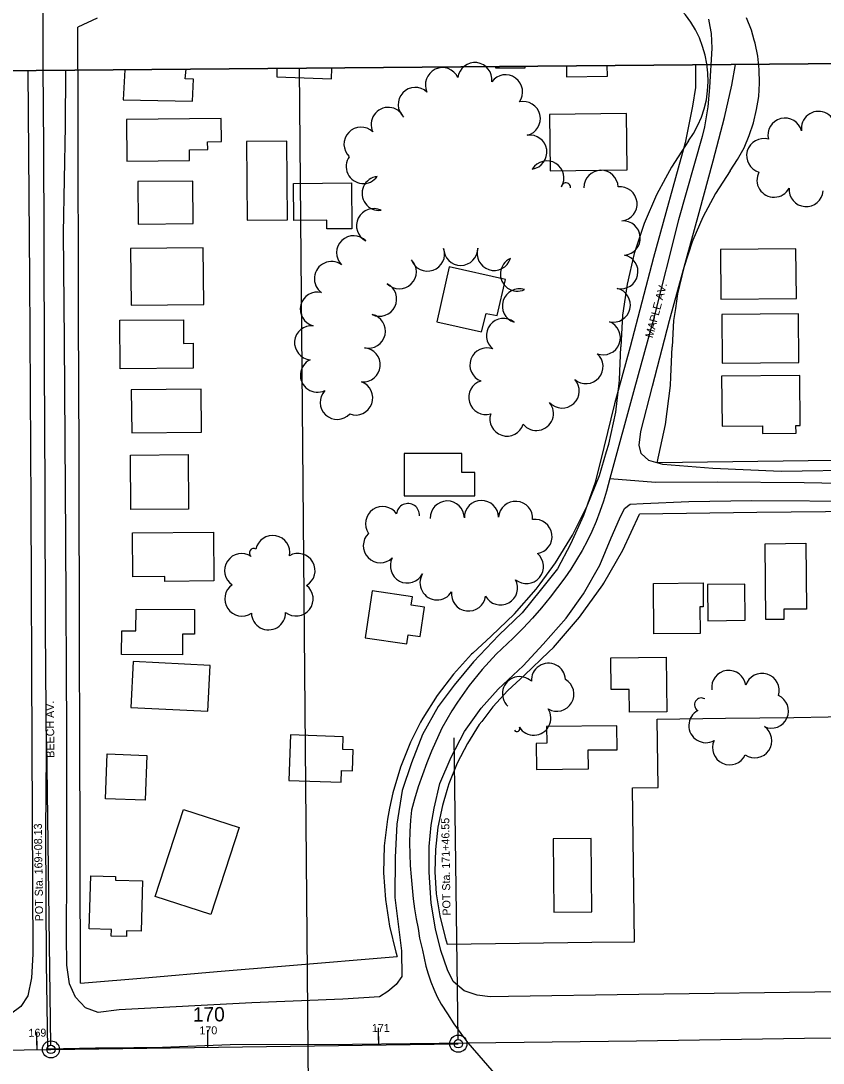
# Model space of a CAD drawing. Extents: x -2233 to 187241, y 4582 to 150524.
# Drawn here: x 116828 to 117297, y 59523 to 60132 of the extents above; entities that cross this region are included whole.
import ezdxf

# ---------------------------------------------------------------- set-up
doc = ezdxf.new("R2010")
doc.units = 0
for name, color, linetype in [('60', 7, 'Continuous'), ('BLDG', 7, 'Continuous'), ('GE_X_CL_100', 7, 'Continuous'), ('GE_X_CL_20', 7, 'Continuous'), ('GE_X_CL_2000', 7, 'Continuous'), ('GE_X_CL_50', 7, 'Continuous'), ('GRID', 7, 'Continuous'), ('ROAD', 7, 'Continuous'), ('ROAD-NAME', 7, 'Continuous'), ('RW_X_Fee_RW', 7, 'Continuous'), ('TREES', 7, 'Continuous')]:
    doc.layers.add(name, color=color, linetype=linetype)

msp = doc.modelspace()

# ---------------------------------------------------------------- linework, layer by layer
at = {"layer": '60'}
msp.add_line((114990.89, 60087.23), (119990.7, 60130.86), dxfattribs=at)
at = {"layer": 'BLDG'}
for points in [[(117105.7, 60105.68), (117105.73, 60105.01), (117122.97, 60104.93), (117123, 60105.83)], [(117147.16, 60106.04), (117147.27, 60099.76), (117171.27, 60100.08), (117171.06, 60106.25)], [(116888.84, 60103.79), (116887.88, 60086.19), (116928.33, 60085.4), (116928.99, 60098.28), (116924.17, 60098.45), (116924.61, 60104.1)], [(116977.78, 60104.57), (116977.8, 60099.72), (117009.7, 60098.52), (117009.87, 60104.85)]]:
    msp.add_lwpolyline(points, dxfattribs=at)
for points in [[(116889.9, 60050.42), (116926.65, 60050.74), (116926.6, 60057.08), (116937.26, 60057.17), (116937.22, 60061.72), (116945.35, 60061.79), (116945.23, 60075.25), (116889.68, 60074.77)], [(117137.78, 60044.74), (117182.74, 60045.29), (117182.34, 60078.21), (117137.37, 60077.65)], [(116983.93, 60016.1), (116983.53, 60062.14), (116960.06, 60061.93), (116960.46, 60015.89)], [(116896.63, 60013.54), (116928.79, 60013.83), (116928.57, 60038.77), (116896.41, 60038.49)], [(117021.39, 60037.61), (117021.63, 60010.89), (117007.04, 60010.76), (117006.99, 60015.84), (116987.67, 60015.67), (116987.48, 60037.32)], [(116892.45, 59966.12), (116935, 59966.49), (116934.71, 59999.65), (116892.16, 59999.28)], [(117237.64, 59969.63), (117281.76, 59970.01), (117281.51, 59999.18), (117237.39, 59998.8)], [(117071.34, 59956.47), (117097.57, 59950.55), (117100.19, 59961.34), (117106.69, 59960.09), (117111.46, 59981.19), (117078.59, 59988.6)], [(117238.4, 59932.21), (117283.31, 59932.61), (117283.06, 59961.14), (117238.15, 59960.74)], [(116885.86, 59957.3), (116923.08, 59957.62), (116923.2, 59943.81), (116928.68, 59943.86), (116928.8, 59929.31), (116886.11, 59928.94)], [(117238.27, 59895.41), (117261.88, 59895.62), (117261.92, 59891.07), (117281.57, 59891.24), (117281.53, 59895.74), (117284.08, 59895.76), (117283.83, 59924.97), (117238.02, 59924.57)], [(116892.79, 59891.55), (116933.63, 59891.9), (116933.41, 59916.97), (116892.57, 59916.62)], [(117052.32, 59854.61), (117093.61, 59854.61), (117093.61, 59868.35), (117086.08, 59868.35), (117086.08, 59879.46), (117052.32, 59879.46)], [(116925.78, 59878.71), (116926.05, 59846.84), (116892.3, 59846.54), (116892.02, 59878.42)], [(116940.88, 59804.84), (116912.2, 59804.59), (116912.18, 59807.34), (116893.5, 59807.18), (116893.27, 59833.04), (116940.63, 59833.45)], [(117287.34, 59826.84), (117287.68, 59788.38), (117274.41, 59788.26), (117274.46, 59782.3), (117263.97, 59782.21), (117263.58, 59826.63)], [(117227.14, 59803.64), (117227.26, 59789.68), (117225.36, 59789.67), (117225.5, 59774.14), (117198.36, 59773.9), (117198.1, 59803.39)], [(117251.79, 59781.79), (117251.61, 59802.86), (117229.75, 59802.67), (117229.94, 59781.59)], [(117053.85, 59768.03), (117054.62, 59773.37), (117061.68, 59772.36), (117064.16, 59789.57), (117056.43, 59790.68), (117057.13, 59795.57), (117033.44, 59798.99), (117029.48, 59771.55)], [(116887.01, 59775.7), (116895.24, 59775.64), (116895.33, 59788.4), (116929.59, 59788.15), (116929.48, 59773.74), (116922.51, 59773.79), (116922.43, 59761.59), (116886.91, 59761.84)], [(116892.35, 59730.85), (116937.35, 59728.6), (116938.68, 59755.4), (116893.68, 59757.65)], [(117205.91, 59728.17), (117184.08, 59727.98), (117183.96, 59741.38), (117173.31, 59741.29), (117173.15, 59759.93), (117205.63, 59760.21)], [(116984.74, 59688.11), (117015.31, 59687.04), (117015.56, 59694), (117022.02, 59693.77), (117022.46, 59706.08), (117016.29, 59706.3), (117016.56, 59713.66), (116985.68, 59714.74)], [(117135.65, 59709.86), (117129.5, 59709.81), (117129.63, 59694.6), (117160.11, 59694.86), (117160.01, 59705.98), (117176.86, 59706.13), (117176.74, 59720.13), (117135.56, 59719.77)], [(116901.67, 59702.72), (116900.64, 59676.55), (116877.47, 59677.45), (116878.5, 59703.62)], [(116923.12, 59671.12), (116955.62, 59660.55), (116939.06, 59609.67), (116906.56, 59620.25)], [(117162.03, 59611.31), (117161.65, 59654.23), (117139.41, 59654.04), (117139.79, 59611.11)], [(116883.3, 59631.99), (116883.24, 59629.73), (116899.18, 59629.32), (116898.43, 59599.97), (116889.77, 59600.19), (116889.68, 59596.8), (116880.78, 59597.02), (116880.88, 59601.02), (116867.98, 59601.35), (116868.78, 59632.37)]]:
    msp.add_lwpolyline(points, close=True, dxfattribs=at)
at = {"layer": 'GE_X_CL_100'}
for p, q in [((116837.41, 59530.7), (116837.27, 59540.7)), ((116937.4, 59532.09), (116937.26, 59542.09)), ((117037.39, 59533.48), (117037.25, 59543.48))]:
    msp.add_line(p, q, dxfattribs=at)
for centre in [(117083.94, 59534.13), (116845.54, 59530.81)]:
    msp.add_circle(centre, 5, dxfattribs=at)
at = {"layer": 'GE_X_CL_20'}
for p, q in [((116845.54, 59530.81), (117083.94, 59534.13)), ((116459.67, 59525.44), (116845.54, 59530.81))]:
    msp.add_line(p, q, dxfattribs=at)
at = {"layer": 'GE_X_CL_2000'}
for p, q in [((116845.54, 59530.81), (117083.94, 59534.13)), ((116459.67, 59525.44), (116845.54, 59530.81))]:
    msp.add_line(p, q, dxfattribs=at)
for points in [[(116840.71, 60140.35), (116840.76, 60105.37), (116841.17, 60058.86), (116841.41, 60004.82), (116841.52, 59931.57), (116841.96, 59857.96), (116842.08, 59777.38), (116842.69, 59704.76), (116842.25, 59657.72), (116842.7, 59581.45), (116843.55, 59531.09)], [(117230.29, 60133.4), (117231.19, 60129.25), (117231.83, 60125.06), (117232.2, 60120.83), (117232.31, 60116.48), (117230.87, 60093.51), (117229.88, 60082.08), (117229.07, 60076.27), (117228.02, 60070.49), (117226.73, 60064.77), (117212.74, 60016.05), (117198.17, 59957.94), (117186.98, 59917.69), (117172.68, 59864.81)], [(117172.68, 59864.81), (117199.4, 59862.58), (117235.41, 59862.88), (117286.3, 59862.44), (117327.41, 59861.65), (117378.43, 59862.74), (117412.31, 59864.32), (117453.32, 59865.4), (117500.32, 59866.16), (117563.97, 59866.92), (117594.05, 59867.09)], [(117172.68, 59864.81), (117170.68, 59857.42), (117168.87, 59851.44), (117166.82, 59845.47), (117164.53, 59839.59), (117162.02, 59833.81), (117159.28, 59828.13), (117156.33, 59822.56), (117153.15, 59817.11), (117149.77, 59811.78), (117146.18, 59806.6), (117137.71, 59795.37), (117132.62, 59789.11), (117127.32, 59783.02), (117121.79, 59777.11), (117116.07, 59771.42), (117106.07, 59761.9), (117101.92, 59757.55), (117097.92, 59753.09), (117090.37, 59743.76), (117083.42, 59733.97), (117080.18, 59728.91), (117077.12, 59723.76), (117074.3, 59718.65), (117068.25, 59705.24), (117065.48, 59698.34), (117062.9, 59691.36), (117060.51, 59684.32), (117058.32, 59677.2), (117056.52, 59670.73), (117055.99, 59664.82), (117055.61, 59658.2), (117055.45, 59651.58), (117055.51, 59644.95), (117055.77, 59638.34), (117056.27, 59631.75), (117057.57, 59618.84), (117058.34, 59613), (117059.31, 59607.2), (117060.5, 59601.44), (117061.31, 59595.93), (117062.96, 59588.83), (117063.86, 59584.15), (117064.98, 59579.51), (117066.32, 59574.92), (117067.88, 59570.4), (117069.66, 59565.96), (117071.64, 59561.61), (117073.83, 59557.35), (117077.52, 59551.52), (117081.36, 59545.79), (117085.34, 59540.15), (117089.46, 59534.61)], [(117089.46, 59534.61), (117188.13, 59535.82), (117286.59, 59537.3), (117403.02, 59538.61), (117495.02, 59539.89), (117597.94, 59541.18), (117683.75, 59542.64), (117758.76, 59543.31), (117864.38, 59544.34), (117977.18, 59546.65), (118072.64, 59547.94), (118190.66, 59549.1), (118291.12, 59550.63), (118437.23, 59552.52), (118581.72, 59553.96), (118618.87, 59554.62), (118637.67, 59554.95)], [(116843.55, 59531.09), (116871.7, 59531.64), (116877.16, 59531.75), (116910.84, 59532.16), (116950.34, 59533.71), (117021.97, 59533.95), (117089.46, 59534.61)], [(117089.46, 59534.61), (117107.54, 59514.04), (117117.08, 59502.34), (117121.21, 59496.92), (117145.67, 59459.68), (117167.85, 59430.52), (117227.56, 59355.19), (117330.54, 59230.76), (117418.75, 59121.97), (117497.33, 59024.25), (117527.76, 58987.99)]]:
    msp.add_lwpolyline(points, dxfattribs=at)
at = {"layer": 'GE_X_CL_50'}
for p, q in [((116845.5, 59533.31), (116843.03, 59710.69)), ((117083.9, 59536.63), (117081.44, 59713.13)), ((117037.39, 59533.48), (117037.32, 59538.48)), ((116837.41, 59530.7), (116837.34, 59535.7)), ((116937.4, 59532.09), (116937.33, 59537.09))]:
    msp.add_line(p, q, dxfattribs=at)
for centre in [(116845.54, 59530.81), (117083.94, 59534.13)]:
    msp.add_circle(centre, 2.5, dxfattribs=at)
at = {"layer": 'GRID'}
for p, q in [((119990.7, 60130.86), (114990.89, 60087.23)), ((116990.82, 60104.68), (117014.36, 57407.01))]:
    msp.add_line(p, q, dxfattribs=at)
at = {"layer": 'ROAD'}
for points in [[(117222.67, 60106.7), (117222.74, 60093.43), (117220.94, 60082.54), (117216.62, 60061.05), (117198.24, 59993.94), (117184.57, 59941.86), (117175.32, 59908.43), (117169.04, 59882.96), (117164.06, 59862.45), (117157.25, 59843.17), (117149.5, 59826.38), (117142.04, 59811.96), (117131.93, 59799.15), (117121.32, 59786.21), (117107.55, 59773.09), (117092.84, 59757.54), (117081.5, 59743.88), (117072.08, 59731.29), (117063.03, 59714.97), (117056.46, 59698.47), (117051.1, 59682.27), (117048.05, 59662.59), (117046.9, 59643.23), (117046.82, 59619.66), (117050.73, 59588.55), (117050.9, 59573.41), (117047.51, 59568.74), (117042.7, 59564.6), (117037.79, 59561.59), (117016.36, 59560.14), (116963.07, 59558.13), (116885.41, 59553.93), (116873.16, 59552.46), (116865.79, 59555.2), (116859.89, 59561.41), (116856.34, 59569.16), (116854.86, 59580.06), (116854.62, 59597.29), (116854.75, 59634.74), (116854.9, 59715.52), (116854.34, 59829.55), (116853.42, 59945.46), (116852.8, 60008.47), (116853.97, 60070.85), (116854.27, 60103.49)], [(117370.72, 59870.41), (117272.94, 59868.92), (117232.79, 59870.61), (117203.64, 59872.91), (117195.52, 59875.19), (117191.01, 59879.35), (117189.84, 59884.19), (117190.72, 59892.33), (117197.67, 59918.78), (117207.52, 59957.11), (117224.95, 60020.33), (117233.05, 60050.61), (117239.78, 60075.92), (117244.04, 60094.87), (117246.22, 60106.91)], [(116832.1, 60103.3), (116833.06, 59981.74), (116833.7, 59849.22), (116834.41, 59708.02), (116835.01, 59586.52), (116834.06, 59572.68), (116832.05, 59562.16), (116827.94, 59555.95), (116821.82, 59551.32)], [(117307.15, 59564.45), (117189.55, 59562.84), (117113.3, 59561.73), (117102.54, 59561.63), (117095.03, 59562.6), (117087.41, 59565.08), (117080.9, 59570.45), (117077.64, 59577.44), (117073.73, 59588.59), (117070.54, 59601.29), (117068.03, 59616.35), (117066.81, 59634.44), (117066.97, 59649.52), (117067.96, 59661.9), (117069.74, 59671.97), (117073.07, 59686.33), (117079.74, 59701.81), (117087.5, 59716.7), (117097.33, 59730.38), (117107.17, 59741.59), (117121.87, 59755.18), (117133.63, 59767.84), (117147.02, 59783.1), (117157.2, 59797.36), (117166.68, 59814.13), (117173.46, 59830), (117178.35, 59841.25), (117181.2, 59847.29), (117184.42, 59849.8), (117192.08, 59850.18), (117218.9, 59851.22), (117255.62, 59851.83), (117323.49, 59851.59)]]:
    msp.add_lwpolyline(points, dxfattribs=at)
at = {"layer": 'RW_X_Fee_RW'}
for p, q in [((116872.63, 60134.06), (116861.23, 60128.76)), ((117200.83, 59683.96), (117200.33, 59723.96)), ((117185.83, 59683.76), (117200.83, 59683.96)), ((117187.03, 59593.76), (117185.83, 59683.76))]:
    msp.add_line(p, q, dxfattribs=at)
for points in [[(117218.73, 60062.26), (117221.63, 60066.66), (117224.13, 60071.36), (117226.23, 60076.16), (117227.75, 60080.92), (117229.13, 60086.26), (117229.83, 60091.46), (117230.23, 60096.76), (117230.03, 60102.06), (117229.43, 60107.26), (117228.43, 60112.46), (117226.93, 60117.46), (117225.03, 60122.46), (117222.73, 60127.16), (117220.03, 60131.66), (117216.93, 60135.96), (117213.43, 60139.86), (117209.73, 60143.56), (117205.63, 60146.86), (117201.23, 60149.86), (117196.63, 60152.46), (117191.83, 60154.56), (117186.83, 60156.36)], [(117243.03, 60044.76), (117247.33, 60051.36), (117251.13, 60058.26), (117254.23, 60065.46), (117256.73, 60072.86), (117258.53, 60080.56), (117259.2, 60084.87), (117259.73, 60088.26), (117260.23, 60096.06), (117260.03, 60103.96), (117259.13, 60111.76), (117257.63, 60119.46), (117257.14, 60121.14), (117255.43, 60126.96), (117252.63, 60134.26)], [(116862.83, 59569.56), (116862.45, 59719.58), (116862.33, 59759.59), (116862.21, 59799.59), (116862.09, 59839.57), (116861.97, 59879.57), (116861.85, 59919.57), (116861.73, 59959.57), (116861.61, 59999.57), (116861.49, 60039.57), (116861.37, 60079.57), (116861.23, 60128.76)], [(117218.73, 60062.26), (117208.63, 60046.86), (117205.18, 60040.48), (117199.93, 60030.76), (117192.73, 60013.86), (117188.27, 60000.41), (117186.93, 59996.36), (117182.73, 59978.46), (117180.03, 59960.36), (117179.03, 59941.81)], [(117243.03, 60044.76), (117234.43, 60031.56), (117227.03, 60017.66), (117221.19, 60004.23), (117220.73, 60003.16), (117215.83, 59988.26), (117212.23, 59972.86), (117210.94, 59964.13), (117209.93, 59957.26), (117209.03, 59941.71)], [(117103.18, 59772.51), (117116.83, 59785.56), (117129.53, 59799.96), (117131.88, 59803.17), (117140.83, 59815.36), (117150.83, 59831.66), (117155.27, 59840.49), (117159.43, 59848.76), (117166.53, 59866.56), (117170.72, 59880.52), (117172.03, 59884.86), (117176.03, 59903.56), (117178.07, 59920.47), (117178.33, 59922.56), (117179.03, 59941.81)], [(117200.23, 59873.96), (117205.23, 59896.36), (117208.13, 59919.06), (117208.33, 59924.17), (117209.03, 59941.71)], [(117607.73, 59879.36), (117543.43, 59878.51), (117503.43, 59877.98), (117463.43, 59877.45), (117423.43, 59876.92), (117383.43, 59876.39), (117343.43, 59875.86), (117303.43, 59875.33), (117200.23, 59873.96)], [(117578.13, 59848.96), (117478.73, 59847.66), (117458.73, 59847.39), (117418.73, 59846.87), (117378.73, 59846.34), (117338.73, 59845.82), (117298.73, 59845.29), (117258.73, 59844.77), (117190.03, 59843.86)], [(117122.68, 59749.71), (117136.82, 59763.27), (117139.63, 59765.96), (117154.83, 59783.66), (117168.43, 59802.56), (117169.01, 59803.57), (117180.13, 59822.76), (117190.03, 59843.86)], [(117103.18, 59772.51), (117092.35, 59762.54), (117091.73, 59761.96), (117081.13, 59750.36), (117071.53, 59737.86), (117063.13, 59724.56), (117061.89, 59722.13), (117056.03, 59710.56), (117050.13, 59695.96), (117045.53, 59680.96), (117043.71, 59671.93), (117042.43, 59665.56), (117040.63, 59649.86), (117040.23, 59634.16), (117041.23, 59618.46), (117043.63, 59602.86), (117047.43, 59587.66), (117048.23, 59585.16)], [(117122.68, 59749.71), (117112.93, 59740.76), (117104.13, 59731.16), (117097.62, 59722.59), (117096.23, 59720.76), (117089.23, 59709.76), (117083.33, 59698.16), (117078.43, 59686.06), (117077.3, 59682.34), (117074.63, 59673.56), (117072.03, 59660.76), (117070.53, 59647.76), (117070.23, 59634.76), (117071.03, 59621.76), (117073.03, 59608.86), (117076.23, 59596.16), (117077.33, 59592.36)], [(117200.33, 59723.96), (117240.33, 59724.5), (117260.33, 59724.77), (117280.33, 59725.04), (117300.33, 59725.31), (117320.33, 59725.58), (117340.33, 59725.85), (117360.33, 59726.12), (117380.33, 59726.39), (117410.33, 59726.79), (117420.33, 59726.92), (117460.33, 59727.46)], [(117077.33, 59592.36), (117162.03, 59593.44), (117187.03, 59593.76)], [(116862.83, 59569.56), (116902.88, 59572.93), (116942.87, 59576.3), (116982.86, 59579.66), (117048.23, 59585.16)]]:
    msp.add_lwpolyline(points, dxfattribs=at)
at = {"layer": 'TREES'}
for centre, radius, start, end in [((117074.63, 60095.08), 10, 25.23091, 205.23091), ((117093.59, 60098.09), 10, 352.80419, 172.80419), ((117111.58, 60090.93), 10, 323.79626, 143.79626), ((117058.76, 60083.51), 10, 46.9689, 226.9689), ((117042.92, 60071.86), 10, 25.68851, 205.68851), ((117121.96, 60075.29), 10, 283.35783, 103.35783), ((117275.12, 60065.62), 10, 14.05561, 194.05561), ((117294.71, 60069.53), 10, 8.51875, 188.51875), ((117027.03, 60060.27), 10, 46.53632, 226.53632), ((117125.75, 60055.67), 10, 278.51144, 98.51144), ((117262.64, 60053.59), 10, 73.87217, 253.87217), ((117028.33, 60047.25), 10, 144.84858, 324.84858), ((117135.75, 60040.54), 10, 328.38184, 148.38184), ((117167.46, 60035.05), 10, 1.27631, 181.27631), ((117268.69, 60039.28), 10, 151.93909, 331.93909), ((117037.64, 60031.56), 10, 96.49495, 276.49495), ((117146.92, 60035.07), 2.67, 355.15916, 175.15916), ((117178.57, 60025.34), 10, 276.38961, 96.38961), ((117287.48, 60033.77), 10, 175.39232, 355.39232), ((117034.34, 60012.66), 10, 63.70298, 243.70298), ((117180.44, 60005.43), 10, 274.34422, 94.34422), ((117022.7, 59996.76), 10, 43.90487, 223.90487), ((117065.9, 59996.05), 10, 199.22805, 19.22805), ((117085.35, 59999.42), 10, 180.46164, 0.46164), ((117104.87, 59996.46), 10, 162.26036, 342.26036), ((117179.07, 59985.68), 10, 257.71673, 77.71673), ((117009.7, 59981.68), 10, 54.55448, 234.55448), ((117049.38, 59985.7), 10, 224.88499, 44.88499), ((117118.57, 59984.32), 10, 114.64386, 294.64386), ((117037.87, 59969.67), 10, 243.74974, 63.74974), ((117001.45, 59963.83), 10, 75.84389, 255.84389), ((117119.66, 59965.71), 10, 72.11364, 252.11364), ((117174.65, 59966.18), 10, 256.74114, 76.74114), ((117031.27, 59950.94), 10, 257.40108, 77.40108), ((116998.1, 59944.18), 10, 84.79321, 264.79321), ((117110.38, 59948.36), 10, 51.56141, 231.56141), ((117168.8, 59947.1), 10, 249.16659, 69.16659), ((117028.2, 59931.22), 10, 264.92171, 84.92171), ((117100.67, 59931.16), 10, 69.61019, 249.61019), ((117001.5, 59925.2), 10, 115.50997, 295.50997), ((117158.65, 59930.23), 10, 228.80055, 48.80055), ((117144.7, 59915.94), 10, 222.58749, 42.58749), ((117013.1, 59909.33), 10, 136.86931, 316.86931), ((117023.86, 59911.88), 10, 249.77964, 69.77964), ((117100.04, 59912.2), 10, 106.55894, 286.55894), ((117129.63, 59902.81), 10, 219.52818, 39.52818), ((117112.4, 59899.53), 10, 162.02522, 342.02522), ((117054.49, 59843.46), 6.66, 355.15314, 175.15314), ((117077.47, 59841.6), 10, 0.923, 180.923), ((117097.47, 59841.92), 10, 0.923, 180.923), ((117117.45, 59841.4), 10, 356.11298, 176.11298), ((117039.62, 59838.34), 10, 34.61265, 214.61265), ((117128.81, 59830.82), 10, 277.99204, 97.99204), ((116975.3, 59821.46), 10, 349.13976, 169.13976), ((117038.33, 59825.47), 10, 134.01016, 314.01016), ((116957.18, 59810.88), 10, 56.34731, 236.34731), ((116964.1, 59821.28), 2.49, 56.32878, 236.32878), ((116990.12, 59810.91), 10, 299.97408, 119.97408), ((117123.82, 59813.23), 10, 230.29258, 50.29258), ((117054.13, 59813.62), 10, 152.25075, 332.25075), ((117071.5, 59803.73), 10, 148.42028, 328.42028), ((116957.25, 59794.28), 10, 124.09373, 304.09373), ((116988.98, 59794.35), 10, 232.16403, 52.16403), ((117108.64, 59800.75), 10, 208.55265, 28.55265), ((117089.94, 59797.23), 10, 172.75851, 352.75851), ((116972.85, 59786.23), 10, 181.31753, 1.31753), ((117136.66, 59746.67), 10, 3.21221, 183.21221), ((117242.22, 59742.5), 10, 7.30313, 187.30313), ((117119.77, 59738.87), 10, 46.34529, 226.34529), ((117141.59, 59738.6), 10, 239.66386, 59.66386), ((117261.69, 59740.81), 10, 342.77567, 162.77567), ((117226.15, 59732.39), 3.98, 58.30259, 238.30259), ((117267.14, 59728.73), 10, 245.78971, 65.78971), ((117128.11, 59724.6), 10, 212.47373, 32.47373), ((117228.84, 59720.22), 10, 118.56454, 298.56454), ((117118.25, 59718.38), 1.66, 210.97226, 30.97226), ((117257.42, 59711.34), 10, 235.75063, 55.75062), ((117242.7, 59707.26), 10, 155.26651, 335.26651)]:
    msp.add_arc(centre, radius, start, end, dxfattribs=at)

# ---------------------------------------------------------------- texts
at = {"layer": 'GE_X_CL_100'}
msp.add_text('170', height=8.4, rotation=0.79813, dxfattribs=at).set_placement((116928.58, 59546.97))
at = {"layer": 'GE_X_CL_50'}
for s, rotation, p in [('POT Sta. 171+46.55', 90.79813, (117079.39, 59609.08)), ('POT Sta. 169+08.13', 90.79813, (116841, 59605.75)), ('170', 0.79813, (116932.46, 59539.52)), ('171', 0.79813, (117033.39, 59540.93)), ('169', 0.79813, (116832.43, 59538.13))]:
    msp.add_text(s, height=4.68, rotation=rotation, dxfattribs=at).set_placement(p)
at = {"layer": 'ROAD-NAME'}
for s, rotation, p in [('MAPLE AV.', 75.07682, (117197.69, 59946.63)), ('BEECH AV.', 90.5, (116847.55, 59701.41))]:
    msp.add_text(s, height=4.68, rotation=rotation, dxfattribs=at).set_placement(p)

doc.saveas('drawing.dxf')
